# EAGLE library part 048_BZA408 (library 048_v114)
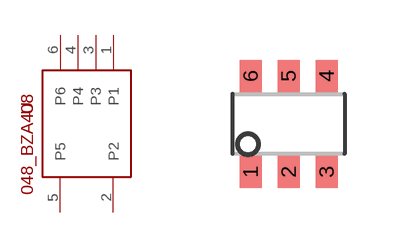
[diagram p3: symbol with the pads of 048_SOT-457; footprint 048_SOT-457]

Designator prefix -

## 048_BZA408  [048_SOT-457]
1  P1
2  P2
3  P3
4  P4  pwr
5  P5
6  P6

## Footprint 048_SOT-457 (pad centres in mm)
smd 0.55 x 0.8: 1 -0.95,-1.2; 2 0,-1.2; 3 0.95,-1.2; 4 0.95,1.2; 5 0,1.2; 6 -0.95,1.2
